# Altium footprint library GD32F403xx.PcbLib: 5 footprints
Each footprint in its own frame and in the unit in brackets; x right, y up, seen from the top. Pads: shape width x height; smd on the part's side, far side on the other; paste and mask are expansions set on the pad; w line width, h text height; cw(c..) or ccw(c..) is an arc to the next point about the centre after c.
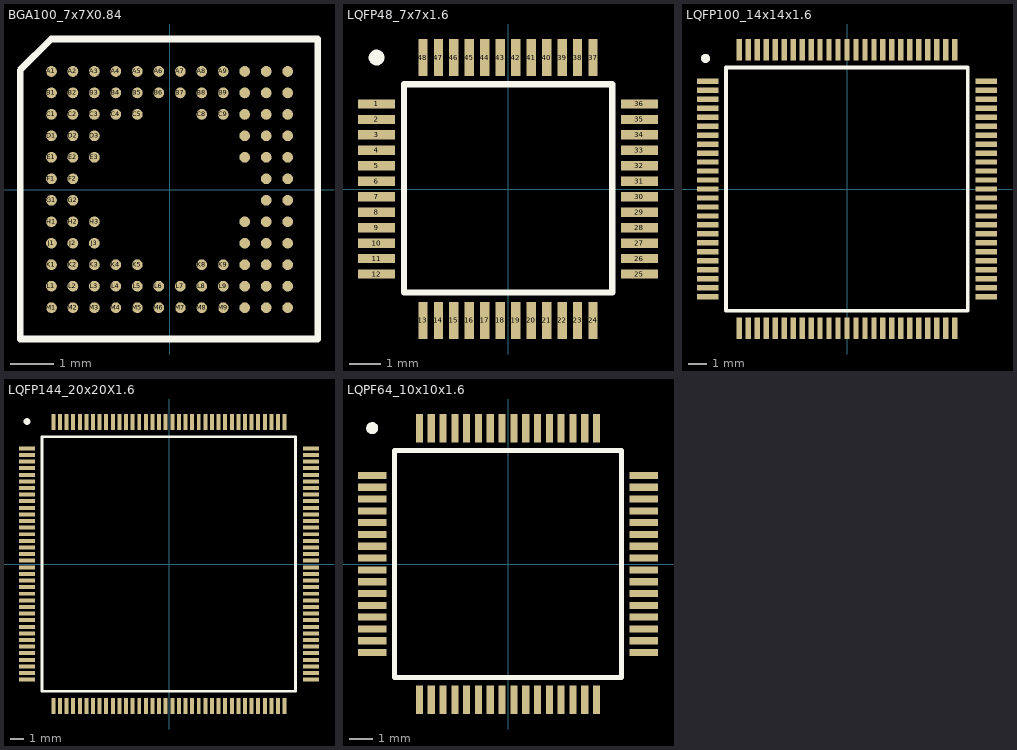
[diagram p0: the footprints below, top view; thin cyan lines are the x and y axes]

## BGA100_7x7X0.84 [mm]
pads (100):
  round 0.25 smd mask+0.05: A1(-2.75,2.75) A2(-2.25,2.75) A3(-1.75,2.75) A4(-1.25,2.75) A5(-0.75,2.75) A6(-0.25,2.75) A7(0.25,2.75) A8(0.75,2.75) A9(1.25,2.75) A10(1.75,2.75) A11(2.25,2.75) A12(2.75,2.75) B1(-2.75,2.25) B2(-2.25,2.25) B3(-1.75,2.25) B4(-1.25,2.25) B5(-0.75,2.25) B6(-0.25,2.25) B7(0.25,2.25) B8(0.75,2.25) B9(1.25,2.25) B10(1.75,2.25) B11(2.25,2.25) B12(2.75,2.25) C1(-2.75,1.75) C2(-2.25,1.75) C3(-1.75,1.75) C4(-1.25,1.75) C5(-0.75,1.75) C8(0.75,1.75) C9(1.25,1.75) C10(1.75,1.75) C11(2.25,1.75) C12(2.75,1.75) D1(-2.75,1.25) D2(-2.25,1.25) D3(-1.75,1.25) D10(1.75,1.25) D11(2.25,1.25) D12(2.75,1.25) E1(-2.75,0.75) E2(-2.25,0.75) E3(-1.75,0.75) E10(1.75,0.75) E11(2.25,0.75) E12(2.75,0.75) F1(-2.75,0.25) F2(-2.25,0.25) F11(2.25,0.25) F12(2.75,0.25) G1(-2.75,-0.25) G2(-2.25,-0.25) G11(2.25,-0.25) G12(2.75,-0.25) H1(-2.75,-0.75) H2(-2.25,-0.75) H3(-1.75,-0.75) H10(1.75,-0.75) H11(2.25,-0.75) H12(2.75,-0.75) J1(-2.75,-1.25) J2(-2.25,-1.25) J3(-1.75,-1.25) J10(1.75,-1.25) J11(2.25,-1.25) J12(2.75,-1.25) K1(-2.75,-1.75) K2(-2.25,-1.75) K3(-1.75,-1.75) K4(-1.25,-1.75) K5(-0.75,-1.75) K8(0.75,-1.75) K9(1.25,-1.75) K10(1.75,-1.75) K11(2.25,-1.75) K12(2.75,-1.75) L1(-2.75,-2.25) L2(-2.25,-2.25) L3(-1.75,-2.25) L4(-1.25,-2.25) L5(-0.75,-2.25) L6(-0.25,-2.25) L7(0.25,-2.25) L8(0.75,-2.25) L9(1.25,-2.25) L10(1.75,-2.25) L11(2.25,-2.25) L12(2.75,-2.25) M1(-2.75,-2.75) M2(-2.25,-2.75) M3(-1.75,-2.75) M4(-1.25,-2.75) M5(-0.75,-2.75) M6(-0.25,-2.75) M7(0.25,-2.75) M8(0.75,-2.75) M9(1.25,-2.75) M10(1.75,-2.75) M11(2.25,-2.75) M12(2.75,-2.75)
Top Overlay:
  lines w0.152: -3.48,-3.48 3.454,-3.48 3.454,3.505 -2.757,3.505 -3.48,2.782 -3.48,-3.48
3D body "BGA100C50P12X12_700X700X84.step": height 0.84, standoff 0, extent -3.5,-3.5 3.5,3.5

## LQFP48_7x7x1.6 [mm]
pads (48):
  rect 1.2x0.3 smd: 1(-4.25,2.75) 2(-4.25,2.25) 3(-4.25,1.75) 4(-4.25,1.25) 5(-4.25,0.75) 6(-4.25,0.25) 7(-4.25,-0.25) 8(-4.25,-0.75) 9(-4.25,-1.25) 10(-4.25,-1.75) 11(-4.25,-2.25) 12(-4.25,-2.75) 25(4.25,-2.75) 26(4.25,-2.25) 27(4.25,-1.75) 28(4.25,-1.25) 29(4.25,-0.75) 30(4.25,-0.25) 31(4.25,0.25) 32(4.25,0.75) 33(4.25,1.25) 34(4.25,1.75) 35(4.25,2.25) 36(4.25,2.75)
  rect 0.3x1.2 smd: 13(-2.75,-4.25) 14(-2.25,-4.25) 15(-1.75,-4.25) 16(-1.25,-4.25) 17(-0.75,-4.25) 18(-0.25,-4.25) 19(0.25,-4.25) 20(0.75,-4.25) 21(1.25,-4.25) 22(1.75,-4.25) 23(2.25,-4.25) 24(2.75,-4.25) 37(2.75,4.25) 38(2.25,4.25) 39(1.75,4.25) 40(1.25,4.25) 41(0.75,4.25) 42(0.25,4.25) 43(-0.25,4.25) 44(-0.75,4.25) 45(-1.25,4.25) 46(-1.75,4.25) 47(-2.25,4.25) 48(-2.75,4.25)
Top Overlay:
  circle w0.254: c-4.25,4.25 r0.127
  lines w0.203: -3.361,-3.346 3.37,-3.346 3.37,3.385 -3.361,3.385 -3.361,-3.346
3D body "TSQFP50P900X900X160-48N.step": height 1.6, standoff 0, extent -4.5,-4.5 4.5,4.5

## LQFP100_14x14x1.6 [mm]
pads (100):
  rect 1.2x0.3 smd: 1(-7.75,6) 2(-7.75,5.5) 3(-7.75,5) 4(-7.75,4.5) 5(-7.75,4) 6(-7.75,3.5) 7(-7.75,3) 8(-7.75,2.5) 9(-7.75,2) 10(-7.75,1.5) 11(-7.75,1) 12(-7.75,0.5) 13(-7.75,0) 14(-7.75,-0.5) 15(-7.75,-1) 16(-7.75,-1.5) 17(-7.75,-2) 18(-7.75,-2.5) 19(-7.75,-3) 20(-7.75,-3.5) 21(-7.75,-4) 22(-7.75,-4.5) 23(-7.75,-5) 24(-7.75,-5.5) 25(-7.75,-6) 51(7.75,-6) 52(7.75,-5.5) 53(7.75,-5) 54(7.75,-4.5) 55(7.75,-4) 56(7.75,-3.5) 57(7.75,-3) 58(7.75,-2.5) 59(7.75,-2) 60(7.75,-1.5) 61(7.75,-1) 62(7.75,-0.5) 63(7.75,0) 64(7.75,0.5) 65(7.75,1) 66(7.75,1.5) 67(7.75,2) 68(7.75,2.5) 69(7.75,3) 70(7.75,3.5) 71(7.75,4) 72(7.75,4.5) 73(7.75,5) 74(7.75,5.5) 75(7.75,6)
  rect 0.3x1.2 smd: 26(-6,-7.75) 27(-5.5,-7.75) 28(-5,-7.75) 29(-4.5,-7.75) 30(-4,-7.75) 31(-3.5,-7.75) 32(-3,-7.75) 33(-2.5,-7.75) 34(-2,-7.75) 35(-1.5,-7.75) 36(-1,-7.75) 37(-0.5,-7.75) 38(0,-7.75) 39(0.5,-7.75) 40(1,-7.75) 41(1.5,-7.75) 42(2,-7.75) 43(2.5,-7.75) 44(3,-7.75) 45(3.5,-7.75) 46(4,-7.75) 47(4.5,-7.75) 48(5,-7.75) 49(5.5,-7.75) 50(6,-7.75) 76(6,7.75) 77(5.5,7.75) 78(5,7.75) 79(4.5,7.75) 80(4,7.75) 81(3.5,7.75) 82(3,7.75) 83(2.5,7.75) 84(2,7.75) 85(1.5,7.75) 86(1,7.75) 87(0.5,7.75) 88(0,7.75) 89(-0.5,7.75) 90(-1,7.75) 91(-1.5,7.75) 92(-2,7.75) 93(-2.5,7.75) 94(-3,7.75) 95(-3.5,7.75) 96(-4,7.75) 97(-4.5,7.75) 98(-5,7.75) 99(-5.5,7.75) 100(-6,7.75)
Top Overlay:
  circle w0.254: c-7.877,7.27 r0.127
  lines w0.203: -6.734,-6.782 -6.734,6.762 6.728,6.762 6.728,-6.782 -6.734,-6.782
3D body "TSQFP50P1600X1600X160-100N.step": height 1.6, standoff 0, extent -8,-8 8,8

## LQFP144_20x20X1.6 [mm]
pads (144):
  rect 1.2x0.3 smd: 1(-10.75,8.75) 2(-10.75,8.25) 3(-10.75,7.75) 4(-10.75,7.25) 5(-10.75,6.75) 6(-10.75,6.25) 7(-10.75,5.75) 8(-10.75,5.25) 9(-10.75,4.75) 10(-10.75,4.25) 11(-10.75,3.75) 12(-10.75,3.25) 13(-10.75,2.75) 14(-10.75,2.25) 15(-10.75,1.75) 16(-10.75,1.25) 17(-10.75,0.75) 18(-10.75,0.25) 19(-10.75,-0.25) 20(-10.75,-0.75) 21(-10.75,-1.25) 22(-10.75,-1.75) 23(-10.75,-2.25) 24(-10.75,-2.75) 25(-10.75,-3.25) 26(-10.75,-3.75) 27(-10.75,-4.25) 28(-10.75,-4.75) 29(-10.75,-5.25) 30(-10.75,-5.75) 31(-10.75,-6.25) 32(-10.75,-6.75) 33(-10.75,-7.25) 34(-10.75,-7.75) 35(-10.75,-8.25) 36(-10.75,-8.75) 73(10.75,-8.75) 74(10.75,-8.25) 75(10.75,-7.75) 76(10.75,-7.25) 77(10.75,-6.75) 78(10.75,-6.25) 79(10.75,-5.75) 80(10.75,-5.25) 81(10.75,-4.75) 82(10.75,-4.25) 83(10.75,-3.75) 84(10.75,-3.25) 85(10.75,-2.75) 86(10.75,-2.25) 87(10.75,-1.75) 88(10.75,-1.25) 89(10.75,-0.75) 90(10.75,-0.25) 91(10.75,0.25) 92(10.75,0.75) 93(10.75,1.25) 94(10.75,1.75) 95(10.75,2.25) 96(10.75,2.75) 97(10.75,3.25) 98(10.75,3.75) 99(10.75,4.25) 100(10.75,4.75) 101(10.75,5.25) 102(10.75,5.75) 103(10.75,6.25) 104(10.75,6.75) 105(10.75,7.25) 106(10.75,7.75) 107(10.75,8.25) 108(10.75,8.75)
  rect 0.3x1.2 smd: 37(-8.75,-10.75) 38(-8.25,-10.75) 39(-7.75,-10.75) 40(-7.25,-10.75) 41(-6.75,-10.75) 42(-6.25,-10.75) 43(-5.75,-10.75) 44(-5.25,-10.75) 45(-4.75,-10.75) 46(-4.25,-10.75) 47(-3.75,-10.75) 48(-3.25,-10.75) 49(-2.75,-10.75) 50(-2.25,-10.75) 51(-1.75,-10.75) 52(-1.25,-10.75) 53(-0.75,-10.75) 54(-0.25,-10.75) 55(0.25,-10.75) 56(0.75,-10.75) 57(1.25,-10.75) 58(1.75,-10.75) 59(2.25,-10.75) 60(2.75,-10.75) 61(3.25,-10.75) 62(3.75,-10.75) 63(4.25,-10.75) 64(4.75,-10.75) 65(5.25,-10.75) 66(5.75,-10.75) 67(6.25,-10.75) 68(6.75,-10.75) 69(7.25,-10.75) 70(7.75,-10.75) 71(8.25,-10.75) 72(8.75,-10.75) 109(8.75,10.75) 110(8.25,10.75) 111(7.75,10.75) 112(7.25,10.75) 113(6.75,10.75) 114(6.25,10.75) 115(5.75,10.75) 116(5.25,10.75) 117(4.75,10.75) 118(4.25,10.75) 119(3.75,10.75) 120(3.25,10.75) 121(2.75,10.75) 122(2.25,10.75) 123(1.75,10.75) 124(1.25,10.75) 125(0.75,10.75) 126(0.25,10.75) 127(-0.25,10.75) 128(-0.75,10.75) 129(-1.25,10.75) 130(-1.75,10.75) 131(-2.25,10.75) 132(-2.75,10.75) 133(-3.25,10.75) 134(-3.75,10.75) 135(-4.25,10.75) 136(-4.75,10.75) 137(-5.25,10.75) 138(-5.75,10.75) 139(-6.25,10.75) 140(-6.75,10.75) 141(-7.25,10.75) 142(-7.75,10.75) 143(-8.25,10.75) 144(-8.75,10.75)
Top Overlay:
  circle w0.254: c-10.75,10.782 r0.127
  lines w0.203: -9.607,-9.627 9.57,-9.627 9.57,9.639 -9.607,9.639 -9.607,-9.627
3D body "TSQFP50P2200X2200X160-144N.step": height 1.6, standoff 0, extent -11,-11 11,11

## LQPF64_10x10x1.6 [mm]
pads (64):
  rect 1.2x0.3 smd: 1(-5.75,3.75) 2(-5.75,3.25) 3(-5.75,2.75) 4(-5.75,2.25) 5(-5.75,1.75) 6(-5.75,1.25) 7(-5.75,0.75) 8(-5.75,0.25) 9(-5.75,-0.25) 10(-5.75,-0.75) 11(-5.75,-1.25) 12(-5.75,-1.75) 13(-5.75,-2.25) 14(-5.75,-2.75) 15(-5.75,-3.25) 16(-5.75,-3.75) 33(5.75,-3.75) 34(5.75,-3.25) 35(5.75,-2.75) 36(5.75,-2.25) 37(5.75,-1.75) 38(5.75,-1.25) 39(5.75,-0.75) 40(5.75,-0.25) 41(5.75,0.25) 42(5.75,0.75) 43(5.75,1.25) 44(5.75,1.75) 45(5.75,2.25) 46(5.75,2.75) 47(5.75,3.25) 48(5.75,3.75)
  rect 0.3x1.2 smd: 17(-3.75,-5.75) 18(-3.25,-5.75) 19(-2.75,-5.75) 20(-2.25,-5.75) 21(-1.75,-5.75) 22(-1.25,-5.75) 23(-0.75,-5.75) 24(-0.25,-5.75) 25(0.25,-5.75) 26(0.75,-5.75) 27(1.25,-5.75) 28(1.75,-5.75) 29(2.25,-5.75) 30(2.75,-5.75) 31(3.25,-5.75) 32(3.75,-5.75) 49(3.75,5.75) 50(3.25,5.75) 51(2.75,5.75) 52(2.25,5.75) 53(1.75,5.75) 54(1.25,5.75) 55(0.75,5.75) 56(0.25,5.75) 57(-0.25,5.75) 58(-0.75,5.75) 59(-1.25,5.75) 60(-1.75,5.75) 61(-2.25,5.75) 62(-2.75,5.75) 63(-3.25,5.75) 64(-3.75,5.75)
Top Overlay:
  circle w0.254: c-5.75,5.75 r0.127
  lines w0.203: -4.801,-4.801 4.801,-4.801 4.801,4.801 -4.801,4.801 -4.801,-4.801
3D body "TSQFP50P1200X1200X160-64N.step": height 1.6, standoff 0, extent -6,-6 6,6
